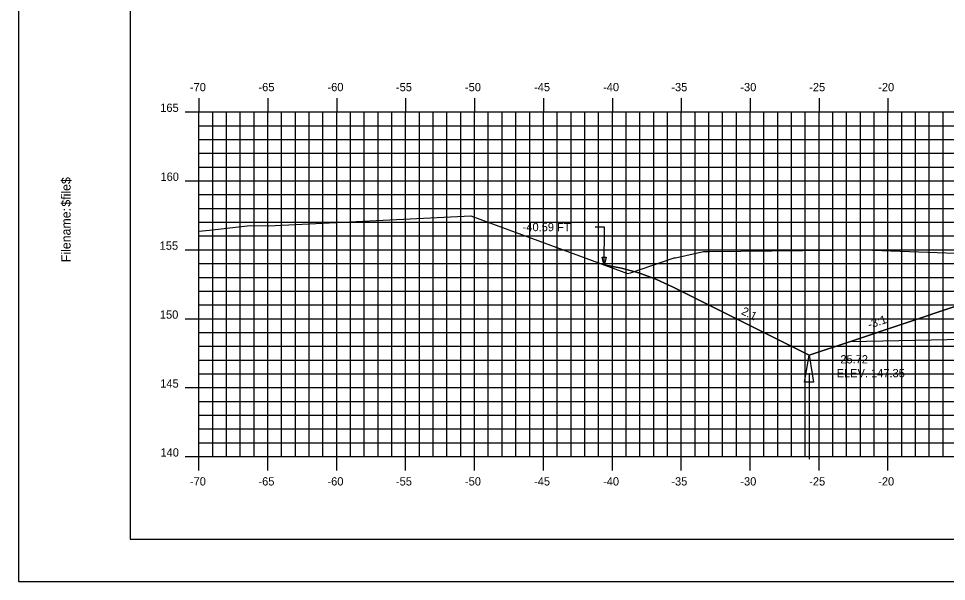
# Model space of a CAD drawing. Extents: x 1143642 to 1143812, y 608981 to 609091.
# Drawn here: x 1143641.7 to 1143709.1, y 608981.3 to 609022.1 of the extents above; entities that cross this region are included whole.
import ezdxf

# ---------------------------------------------------------------- set-up
doc = ezdxf.new("R2010")
doc.units = 0
for name, color, linetype in [('ANNOTATION', 7, 'Continuous'), ('BORDER', 7, 'Continuous'), ('D_Drainage_Ditch_Line', 7, 'Continuous'), ('D_Roadway_SlopeLines', 7, 'Continuous'), ('D_Roadway_SubGrade', 7, 'Continuous'), ('D_Text_Standard', 7, 'Continuous'), ('H_V ANNOTATION', 7, 'Continuous'), ('MAJOR', 7, 'Continuous'), ('MINOR', 7, 'Continuous'), ('PLOT BOUNDARY', 7, 'Continuous'), ('S_Roadway_Centerline', 7, 'Continuous')]:
    doc.layers.add(name, color=color, linetype=linetype)

msp = doc.modelspace()

# ---------------------------------------------------------------- linework, layer by layer
msp.add_lwpolyline([(1143684.248, 609004.24), (1143685.498, 609004), (1143686.748, 609003.651), (1143687.998, 609003.191), (1143689.248, 609002.621), (1143699.112, 608997.689), (1143702.112, 608998.689), (1143709.835, 609001.263), (1143709.836, 609001.263), (1143713.836, 609001.423), (1143724.836, 609001.643), (1143735.836, 609001.423), (1143741.935, 609001.18), (1143749.524, 608998.65), (1143752.524, 608997.65), (1143772.258, 609007.517), (1143773.508, 609008.066), (1143774.758, 609008.464), (1143776.008, 609008.71), (1143777.258, 609008.805)])
at = {"layer": 'BORDER'}
msp.add_lwpolyline([(1143649.836, 608984.335), (1143809.836, 608984.335), (1143809.836, 609089.335), (1143649.836, 609089.335)], close=True, dxfattribs=at)
at = {"layer": 'D_Drainage_Ditch_Line'}
msp.add_line((1143699.112, 608996.377), (1143699.111, 608990.133), dxfattribs=at)
msp.add_lwpolyline([(1143699.44, 608995.72), (1143698.783, 608995.72), (1143699.112, 608997.689)], close=True, dxfattribs=at)
at = {"layer": 'D_Roadway_SlopeLines'}
for points in [[(1143699.112, 608997.689), (1143689.248, 609002.621), (1143687.998, 609003.191), (1143686.748, 609003.651), (1143685.498, 609004), (1143684.248, 609004.24)], [(1143702.112, 608998.689), (1143699.112, 608997.689)]]:
    msp.add_lwpolyline(points, dxfattribs=at)
at = {"layer": 'D_Roadway_SubGrade'}
msp.add_lwpolyline([(1143713.836, 609001.007), (1143713.836, 609001.173), (1143709.836, 609001.013), (1143709.836, 609001.263), (1143709.835, 609001.263), (1143702.112, 608998.689), (1143713.836, 608998.923)], close=True, dxfattribs=at)
at = {"layer": 'D_Text_Standard'}
msp.add_lwpolyline([(1143684.248, 609004.205), (1143684.268, 609006.982), (1143683.588, 609006.982)], dxfattribs=at)
msp.add_lwpolyline([(1143684.248, 609004.205), (1143684.106, 609004.788), (1143684.398, 609004.786)], close=True, dxfattribs=at)
at = {"layer": 'MAJOR'}
for p, q in [((1143654.836, 609016.337), (1143654.836, 609015.335)), ((1143659.836, 609016.337), (1143659.836, 609015.335)), ((1143664.836, 609016.337), (1143664.836, 609015.335)), ((1143669.836, 609016.337), (1143669.836, 609015.335)), ((1143674.836, 609016.337), (1143674.836, 609015.335)), ((1143679.836, 609016.337), (1143679.836, 609015.335)), ((1143684.836, 609016.337), (1143684.836, 609015.335)), ((1143689.836, 609016.337), (1143689.836, 609015.335)), ((1143694.836, 609016.337), (1143694.836, 609015.335)), ((1143699.836, 609016.337), (1143699.836, 609015.335)), ((1143704.836, 609016.337), (1143704.836, 609015.335)), ((1143653.834, 609015.335), (1143654.836, 609015.335)), ((1143654.836, 609015.335), (1143794.836, 609015.335)), ((1143654.836, 608990.335), (1143654.836, 609015.335)), ((1143654.836, 608990.335), (1143654.836, 609015.335)), ((1143654.836, 609015.335), (1143794.836, 609015.335)), ((1143659.836, 608990.335), (1143659.836, 609015.335)), ((1143664.836, 608990.335), (1143664.836, 609015.335)), ((1143669.836, 608990.335), (1143669.836, 609015.335)), ((1143674.836, 608990.335), (1143674.836, 609015.335)), ((1143679.836, 608990.335), (1143679.836, 609015.335)), ((1143684.836, 608990.335), (1143684.836, 609015.335)), ((1143689.836, 608990.335), (1143689.836, 609015.335)), ((1143694.836, 608990.335), (1143694.836, 609015.335)), ((1143699.836, 608990.335), (1143699.836, 609015.335)), ((1143704.836, 608990.335), (1143704.836, 609015.335)), ((1143653.834, 609010.335), (1143654.836, 609010.335)), ((1143654.836, 609010.335), (1143794.836, 609010.335)), ((1143653.834, 609005.335), (1143654.836, 609005.335)), ((1143654.836, 609005.335), (1143794.836, 609005.335)), ((1143653.834, 609000.335), (1143654.836, 609000.335)), ((1143654.836, 609000.335), (1143794.836, 609000.335)), ((1143653.834, 608995.335), (1143654.836, 608995.335)), ((1143654.836, 608995.335), (1143794.836, 608995.335)), ((1143653.834, 608990.335), (1143654.836, 608990.335)), ((1143654.836, 608990.335), (1143794.836, 608990.335)), ((1143654.836, 608990.335), (1143794.836, 608990.335)), ((1143654.836, 608989.333), (1143654.836, 608990.335)), ((1143659.836, 608989.333), (1143659.836, 608990.335)), ((1143664.836, 608989.333), (1143664.836, 608990.335)), ((1143669.836, 608989.333), (1143669.836, 608990.335)), ((1143674.836, 608989.333), (1143674.836, 608990.335)), ((1143679.836, 608989.333), (1143679.836, 608990.335)), ((1143684.836, 608989.333), (1143684.836, 608990.335)), ((1143689.836, 608989.333), (1143689.836, 608990.335)), ((1143694.836, 608989.333), (1143694.836, 608990.335)), ((1143699.836, 608989.333), (1143699.836, 608990.335)), ((1143704.836, 608989.333), (1143704.836, 608990.335))]:
    msp.add_line(p, q, dxfattribs=at)
at = {"layer": 'MINOR'}
for p, q in [((1143655.836, 608990.335), (1143655.836, 609015.335)), ((1143656.836, 608990.335), (1143656.836, 609015.335)), ((1143657.836, 608990.335), (1143657.836, 609015.335)), ((1143658.836, 608990.335), (1143658.836, 609015.335)), ((1143660.836, 608990.335), (1143660.836, 609015.335)), ((1143661.836, 608990.335), (1143661.836, 609015.335)), ((1143662.836, 608990.335), (1143662.836, 609015.335)), ((1143663.836, 608990.335), (1143663.836, 609015.335)), ((1143665.836, 608990.335), (1143665.836, 609015.335)), ((1143666.836, 608990.335), (1143666.836, 609015.335)), ((1143667.836, 608990.335), (1143667.836, 609015.335)), ((1143668.836, 608990.335), (1143668.836, 609015.335)), ((1143670.836, 608990.335), (1143670.836, 609015.335)), ((1143671.836, 608990.335), (1143671.836, 609015.335)), ((1143672.836, 608990.335), (1143672.836, 609015.335)), ((1143673.836, 608990.335), (1143673.836, 609015.335)), ((1143675.836, 608990.335), (1143675.836, 609015.335)), ((1143676.836, 608990.335), (1143676.836, 609015.335)), ((1143677.836, 608990.335), (1143677.836, 609015.335)), ((1143678.836, 608990.335), (1143678.836, 609015.335)), ((1143680.836, 608990.335), (1143680.836, 609015.335)), ((1143681.836, 608990.335), (1143681.836, 609015.335)), ((1143682.836, 608990.335), (1143682.836, 609015.335)), ((1143683.836, 608990.335), (1143683.836, 609015.335)), ((1143685.836, 608990.335), (1143685.836, 609015.335)), ((1143686.836, 608990.335), (1143686.836, 609015.335)), ((1143687.836, 608990.335), (1143687.836, 609015.335)), ((1143688.836, 608990.335), (1143688.836, 609015.335)), ((1143690.836, 608990.335), (1143690.836, 609015.335)), ((1143691.836, 608990.335), (1143691.836, 609015.335)), ((1143692.836, 608990.335), (1143692.836, 609015.335)), ((1143693.836, 608990.335), (1143693.836, 609015.335)), ((1143695.836, 608990.335), (1143695.836, 609015.335)), ((1143696.836, 608990.335), (1143696.836, 609015.335)), ((1143697.836, 608990.335), (1143697.836, 609015.335)), ((1143698.836, 608990.335), (1143698.836, 609015.335)), ((1143700.836, 608990.335), (1143700.836, 609015.335)), ((1143701.836, 608990.335), (1143701.836, 609015.335)), ((1143702.836, 608990.335), (1143702.836, 609015.335)), ((1143703.836, 608990.335), (1143703.836, 609015.335)), ((1143705.836, 608990.335), (1143705.836, 609015.335)), ((1143706.836, 608990.335), (1143706.836, 609015.335)), ((1143707.836, 608990.335), (1143707.836, 609015.335)), ((1143708.836, 608990.335), (1143708.836, 609015.335)), ((1143654.836, 609014.335), (1143794.836, 609014.335)), ((1143654.836, 609014.335), (1143655.838, 609014.335)), ((1143654.836, 609013.335), (1143794.836, 609013.335)), ((1143654.836, 609013.335), (1143655.838, 609013.335)), ((1143654.836, 609012.335), (1143794.836, 609012.335)), ((1143654.836, 609012.335), (1143655.838, 609012.335)), ((1143654.836, 609011.335), (1143794.836, 609011.335)), ((1143654.836, 609011.335), (1143655.838, 609011.335)), ((1143654.836, 609009.335), (1143794.836, 609009.335)), ((1143654.836, 609009.335), (1143655.838, 609009.335)), ((1143654.836, 609008.335), (1143794.836, 609008.335)), ((1143654.836, 609008.335), (1143655.838, 609008.335)), ((1143654.836, 609007.335), (1143794.836, 609007.335)), ((1143654.836, 609007.335), (1143655.838, 609007.335)), ((1143654.836, 609006.335), (1143794.836, 609006.335)), ((1143654.836, 609006.335), (1143655.838, 609006.335)), ((1143654.836, 609004.335), (1143794.836, 609004.335)), ((1143654.836, 609004.335), (1143655.838, 609004.335)), ((1143654.836, 609003.335), (1143794.836, 609003.335)), ((1143654.836, 609003.335), (1143655.838, 609003.335)), ((1143654.836, 609002.335), (1143794.836, 609002.335)), ((1143654.836, 609002.335), (1143655.838, 609002.335)), ((1143654.836, 609001.335), (1143794.836, 609001.335)), ((1143654.836, 609001.335), (1143655.838, 609001.335)), ((1143654.836, 608999.335), (1143794.836, 608999.335)), ((1143654.836, 608999.335), (1143655.838, 608999.335)), ((1143654.836, 608998.335), (1143794.836, 608998.335)), ((1143654.836, 608998.335), (1143655.838, 608998.335)), ((1143654.836, 608997.335), (1143794.836, 608997.335)), ((1143654.836, 608997.335), (1143655.838, 608997.335)), ((1143654.836, 608996.335), (1143794.836, 608996.335)), ((1143654.836, 608996.335), (1143655.838, 608996.335)), ((1143654.836, 608994.335), (1143794.836, 608994.335)), ((1143654.836, 608994.335), (1143655.838, 608994.335)), ((1143654.836, 608993.335), (1143794.836, 608993.335)), ((1143654.836, 608993.335), (1143655.838, 608993.335)), ((1143654.836, 608992.335), (1143794.836, 608992.335)), ((1143654.836, 608992.335), (1143655.838, 608992.335)), ((1143654.836, 608991.335), (1143794.836, 608991.335)), ((1143654.836, 608991.335), (1143655.838, 608991.335))]:
    msp.add_line(p, q, dxfattribs=at)
at = {"layer": 'PLOT BOUNDARY'}
msp.add_lwpolyline([(1143641.743, 608981.276), (1143811.743, 608981.276), (1143811.743, 609091.276), (1143641.743, 609091.276)], close=True, dxfattribs=at)
at = {"layer": 'S_Roadway_Centerline'}
msp.add_lwpolyline([(1143654.836, 609006.691), (1143655.608, 609006.756), (1143658.555, 609007.103), (1143659.891, 609007.074), (1143674.576, 609007.787), (1143675.221, 609007.551), (1143685.937, 609003.62), (1143686.153, 609003.67), (1143689.319, 609004.741), (1143689.412, 609004.755), (1143691.442, 609005.205), (1143691.907, 609005.213), (1143703.158, 609005.328), (1143703.71, 609005.297), (1143714.443, 609004.925)], dxfattribs=at)

# ---------------------------------------------------------------- texts
at = {"layer": 'ANNOTATION'}
for s, rotation, p in [('2:1', 333.43495, (1143694.147, 609000.689)), ('-3:1', 18.43482, (1143703.491, 608999.603))]:
    msp.add_text(s, height=0.6, rotation=rotation, dxfattribs=at).set_placement(p)
at = {"layer": 'BORDER'}
for s, p in [('$file$', (1143645.521, 609008.461)), ('Filename:', (1143645.521, 609004.433))]:
    msp.add_text(s, height=0.6696, rotation=90, dxfattribs=at).set_placement(p)
at = {"layer": 'D_Text_Standard'}
for s, p in [('-40.59 FT', (1143678.326, 609006.682)), ('-25.72', (1143701.112, 608997.089)), ('ELEV. 147.35', (1143701.112, 608996.087))]:
    msp.add_text(s, height=0.6, dxfattribs=at).set_placement(p)
at = {"layer": 'H_V ANNOTATION'}
for s, p in [('-70', (1143654.178, 609016.835)), ('-65', (1143659.154, 609016.835)), ('-60', (1143664.162, 609016.835)), ('-55', (1143669.132, 609016.835)), ('-50', (1143674.14, 609016.835)), ('-45', (1143679.154, 609016.835)), ('-40', (1143684.162, 609016.835)), ('-35', (1143689.116, 609016.835)), ('-30', (1143694.124, 609016.835)), ('-25', (1143699.122, 609016.835)), ('-20', (1143704.13, 609016.835)), ('165', (1143652.025, 609015.335)), ('160', (1143652.041, 609010.335)), ('155', (1143651.982, 609005.335)), ('150', (1143651.998, 609000.335)), ('145', (1143652.025, 608995.335)), ('140', (1143652.041, 608990.335)), ('-70', (1143654.178, 608988.235)), ('-65', (1143659.154, 608988.235)), ('-60', (1143664.162, 608988.235)), ('-55', (1143669.132, 608988.235)), ('-50', (1143674.14, 608988.235)), ('-45', (1143679.154, 608988.235)), ('-40', (1143684.162, 608988.235)), ('-35', (1143689.116, 608988.235)), ('-30', (1143694.124, 608988.235)), ('-25', (1143699.122, 608988.235)), ('-20', (1143704.13, 608988.235))]:
    msp.add_text(s, height=0.6, dxfattribs=at).set_placement(p)
at = {"layer": 'MAJOR'}
msp.add_text('-', height=0.006, dxfattribs=at).set_placement((1143654.832, 608990.335))
at = {"layer": 'S_Roadway_Centerline'}
for s, p in [('L', (1143703.149, 609005.321)), ('C', (1143703.152, 609005.328))]:
    msp.add_text(s, height=0.0146, dxfattribs=at).set_placement(p)

doc.saveas('drawing.dxf')
